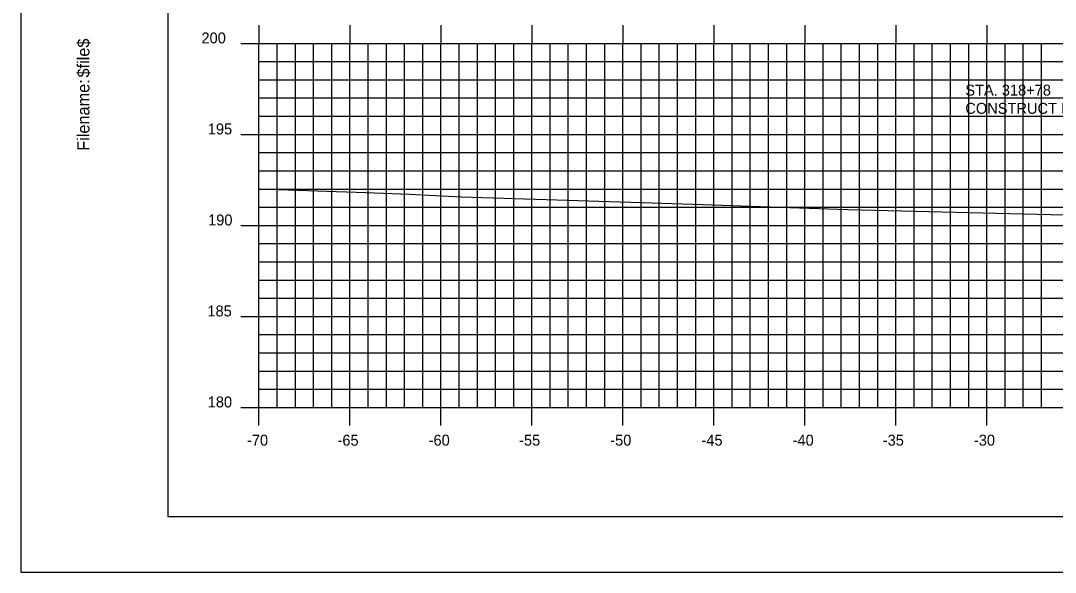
# Model space of a CAD drawing. Extents: x 1139428 to 1139598, y 608981 to 609091.
# Drawn here: x 1139428.4 to 1139485.2, y 608981.3 to 609011.6 of the extents above; entities that cross this region are included whole.
import ezdxf

# ---------------------------------------------------------------- set-up
doc = ezdxf.new("R2010")
doc.units = 0
for name, color, linetype in [('ANNOTATION', 7, 'Continuous'), ('BORDER', 7, 'Continuous'), ('H_V ANNOTATION', 7, 'Continuous'), ('MAJOR', 7, 'Continuous'), ('MINOR', 7, 'Continuous'), ('PLOT BOUNDARY', 7, 'Continuous'), ('S_Roadway_Centerline', 7, 'Continuous')]:
    doc.layers.add(name, color=color, linetype=linetype)

msp = doc.modelspace()

# ---------------------------------------------------------------- linework, layer by layer
at = {"layer": 'BORDER'}
msp.add_lwpolyline([(1139436.462, 608984.335), (1139596.462, 608984.335), (1139596.462, 609089.335), (1139436.462, 609089.335)], close=True, dxfattribs=at)
at = {"layer": 'MAJOR'}
for p, q in [((1139441.462, 609011.337), (1139441.462, 609010.335)), ((1139446.462, 609011.337), (1139446.462, 609010.335)), ((1139451.462, 609011.337), (1139451.462, 609010.335)), ((1139456.462, 609011.337), (1139456.462, 609010.335)), ((1139461.462, 609011.337), (1139461.462, 609010.335)), ((1139466.462, 609011.337), (1139466.462, 609010.335)), ((1139471.462, 609011.337), (1139471.462, 609010.335)), ((1139476.462, 609011.337), (1139476.462, 609010.335)), ((1139481.462, 609011.337), (1139481.462, 609010.335)), ((1139440.46, 609010.335), (1139441.462, 609010.335)), ((1139441.462, 609010.335), (1139581.462, 609010.335)), ((1139441.462, 608990.335), (1139441.462, 609010.335)), ((1139441.462, 608990.335), (1139441.462, 609010.335)), ((1139441.462, 609010.335), (1139581.462, 609010.335)), ((1139446.462, 608990.335), (1139446.462, 609010.335)), ((1139451.462, 608990.335), (1139451.462, 609010.335)), ((1139456.462, 608990.335), (1139456.462, 609010.335)), ((1139461.462, 608990.335), (1139461.462, 609010.335)), ((1139466.462, 608990.335), (1139466.462, 609010.335)), ((1139471.462, 608990.335), (1139471.462, 609010.335)), ((1139476.462, 608990.335), (1139476.462, 609010.335)), ((1139481.462, 608990.335), (1139481.462, 609010.335)), ((1139440.46, 609005.335), (1139441.462, 609005.335)), ((1139441.462, 609005.335), (1139581.462, 609005.335)), ((1139440.46, 609000.335), (1139441.462, 609000.335)), ((1139441.462, 609000.335), (1139581.462, 609000.335)), ((1139440.46, 608995.335), (1139441.462, 608995.335)), ((1139441.462, 608995.335), (1139581.462, 608995.335)), ((1139440.46, 608990.335), (1139441.462, 608990.335)), ((1139441.462, 608990.335), (1139581.462, 608990.335)), ((1139441.462, 608990.335), (1139581.462, 608990.335)), ((1139441.462, 608989.333), (1139441.462, 608990.335)), ((1139446.462, 608989.333), (1139446.462, 608990.335)), ((1139451.462, 608989.333), (1139451.462, 608990.335)), ((1139456.462, 608989.333), (1139456.462, 608990.335)), ((1139461.462, 608989.333), (1139461.462, 608990.335)), ((1139466.462, 608989.333), (1139466.462, 608990.335)), ((1139471.462, 608989.333), (1139471.462, 608990.335)), ((1139476.462, 608989.333), (1139476.462, 608990.335)), ((1139481.462, 608989.333), (1139481.462, 608990.335))]:
    msp.add_line(p, q, dxfattribs=at)
at = {"layer": 'MINOR'}
for p, q in [((1139441.462, 608990.335), (1139441.462, 609010.335)), ((1139442.462, 608990.335), (1139442.462, 609010.335)), ((1139443.462, 608990.335), (1139443.462, 609010.335)), ((1139444.462, 608990.335), (1139444.462, 609010.335)), ((1139445.462, 608990.335), (1139445.462, 609010.335)), ((1139447.462, 608990.335), (1139447.462, 609010.335)), ((1139448.462, 608990.335), (1139448.462, 609010.335)), ((1139449.462, 608990.335), (1139449.462, 609010.335)), ((1139450.462, 608990.335), (1139450.462, 609010.335)), ((1139452.462, 608990.335), (1139452.462, 609010.335)), ((1139453.462, 608990.335), (1139453.462, 609010.335)), ((1139454.462, 608990.335), (1139454.462, 609010.335)), ((1139455.462, 608990.335), (1139455.462, 609010.335)), ((1139457.462, 608990.335), (1139457.462, 609010.335)), ((1139458.462, 608990.335), (1139458.462, 609010.335)), ((1139459.462, 608990.335), (1139459.462, 609010.335)), ((1139460.462, 608990.335), (1139460.462, 609010.335)), ((1139462.462, 608990.335), (1139462.462, 609010.335)), ((1139463.462, 608990.335), (1139463.462, 609010.335)), ((1139464.462, 608990.335), (1139464.462, 609010.335)), ((1139465.462, 608990.335), (1139465.462, 609010.335)), ((1139467.462, 608990.335), (1139467.462, 609010.335)), ((1139468.462, 608990.335), (1139468.462, 609010.335)), ((1139469.462, 608990.335), (1139469.462, 609010.335)), ((1139470.462, 608990.335), (1139470.462, 609010.335)), ((1139472.462, 608990.335), (1139472.462, 609010.335)), ((1139473.462, 608990.335), (1139473.462, 609010.335)), ((1139474.462, 608990.335), (1139474.462, 609010.335)), ((1139475.462, 608990.335), (1139475.462, 609010.335)), ((1139477.462, 608990.335), (1139477.462, 609010.335)), ((1139478.462, 608990.335), (1139478.462, 609010.335)), ((1139479.462, 608990.335), (1139479.462, 609010.335)), ((1139480.462, 608990.335), (1139480.462, 609010.335)), ((1139482.462, 608990.335), (1139482.462, 609010.335)), ((1139483.462, 608990.335), (1139483.462, 609010.335)), ((1139484.462, 608990.335), (1139484.462, 609010.335)), ((1139441.462, 609009.335), (1139581.462, 609009.335)), ((1139441.462, 609009.335), (1139442.464, 609009.335)), ((1139441.462, 609008.335), (1139581.462, 609008.335)), ((1139441.462, 609008.335), (1139442.464, 609008.335)), ((1139441.462, 609007.335), (1139581.462, 609007.335)), ((1139441.462, 609007.335), (1139442.464, 609007.335)), ((1139441.462, 609006.335), (1139581.462, 609006.335)), ((1139441.462, 609006.335), (1139442.464, 609006.335)), ((1139441.462, 609004.335), (1139581.462, 609004.335)), ((1139441.462, 609004.335), (1139442.464, 609004.335)), ((1139441.462, 609003.335), (1139581.462, 609003.335)), ((1139441.462, 609003.335), (1139442.464, 609003.335)), ((1139441.462, 609002.335), (1139581.462, 609002.335)), ((1139441.462, 609002.335), (1139442.464, 609002.335)), ((1139441.462, 609001.335), (1139581.462, 609001.335)), ((1139441.462, 609001.335), (1139442.464, 609001.335)), ((1139441.462, 608999.335), (1139581.462, 608999.335)), ((1139441.462, 608999.335), (1139442.464, 608999.335)), ((1139441.462, 608998.335), (1139581.462, 608998.335)), ((1139441.462, 608998.335), (1139442.464, 608998.335)), ((1139441.462, 608997.335), (1139581.462, 608997.335)), ((1139441.462, 608997.335), (1139442.464, 608997.335)), ((1139441.462, 608996.335), (1139581.462, 608996.335)), ((1139441.462, 608996.335), (1139442.464, 608996.335)), ((1139441.462, 608994.335), (1139581.462, 608994.335)), ((1139441.462, 608994.335), (1139442.464, 608994.335)), ((1139441.462, 608993.335), (1139581.462, 608993.335)), ((1139441.462, 608993.335), (1139442.464, 608993.335)), ((1139441.462, 608992.335), (1139581.462, 608992.335)), ((1139441.462, 608992.335), (1139442.464, 608992.335)), ((1139441.462, 608991.335), (1139581.462, 608991.335)), ((1139441.462, 608991.335), (1139442.464, 608991.335))]:
    msp.add_line(p, q, dxfattribs=at)
at = {"layer": 'PLOT BOUNDARY'}
msp.add_lwpolyline([(1139428.369, 608981.276), (1139598.369, 608981.276), (1139598.369, 609091.276), (1139428.369, 609091.276)], close=True, dxfattribs=at)
at = {"layer": 'S_Roadway_Centerline'}
msp.add_lwpolyline([(1139441.462, 609002.339), (1139447.341, 609002.147), (1139449.739, 609002.053), (1139452.595, 609001.913), (1139463.045, 609001.576), (1139465.842, 609001.488), (1139473.821, 609001.213), (1139480.496, 609001.039), (1139487.202, 609000.883)], dxfattribs=at)

# ---------------------------------------------------------------- texts
at = {"layer": 'ANNOTATION'}
for s, p in [('STA. 318+78', (1139480.278, 609007.468)), ('CONSTRUCT DRIVEWAY BUTT JOINT', (1139480.278, 609006.466))]:
    msp.add_text(s, height=0.6, dxfattribs=at).set_placement(p)
at = {"layer": 'BORDER'}
for s, p in [('$file$', (1139432.147, 609008.461)), ('Filename:', (1139432.147, 609004.433))]:
    msp.add_text(s, height=0.6696, rotation=90, dxfattribs=at).set_placement(p)
at = {"layer": 'H_V ANNOTATION'}
for s, p in [('200', (1139438.302, 609010.335)), ('195', (1139438.651, 609005.335)), ('190', (1139438.667, 609000.335)), ('185', (1139438.629, 608995.335)), ('180', (1139438.645, 608990.335)), ('-70', (1139440.803, 608988.235)), ('-65', (1139445.779, 608988.235)), ('-60', (1139450.787, 608988.235)), ('-55', (1139455.758, 608988.235)), ('-50', (1139460.766, 608988.235)), ('-45', (1139465.779, 608988.235)), ('-40', (1139470.787, 608988.235)), ('-35', (1139475.742, 608988.235)), ('-30', (1139480.75, 608988.235))]:
    msp.add_text(s, height=0.6, dxfattribs=at).set_placement(p)
at = {"layer": 'MAJOR'}
msp.add_text('-', height=0.006, dxfattribs=at).set_placement((1139441.457, 608990.335))

doc.saveas('drawing.dxf')
